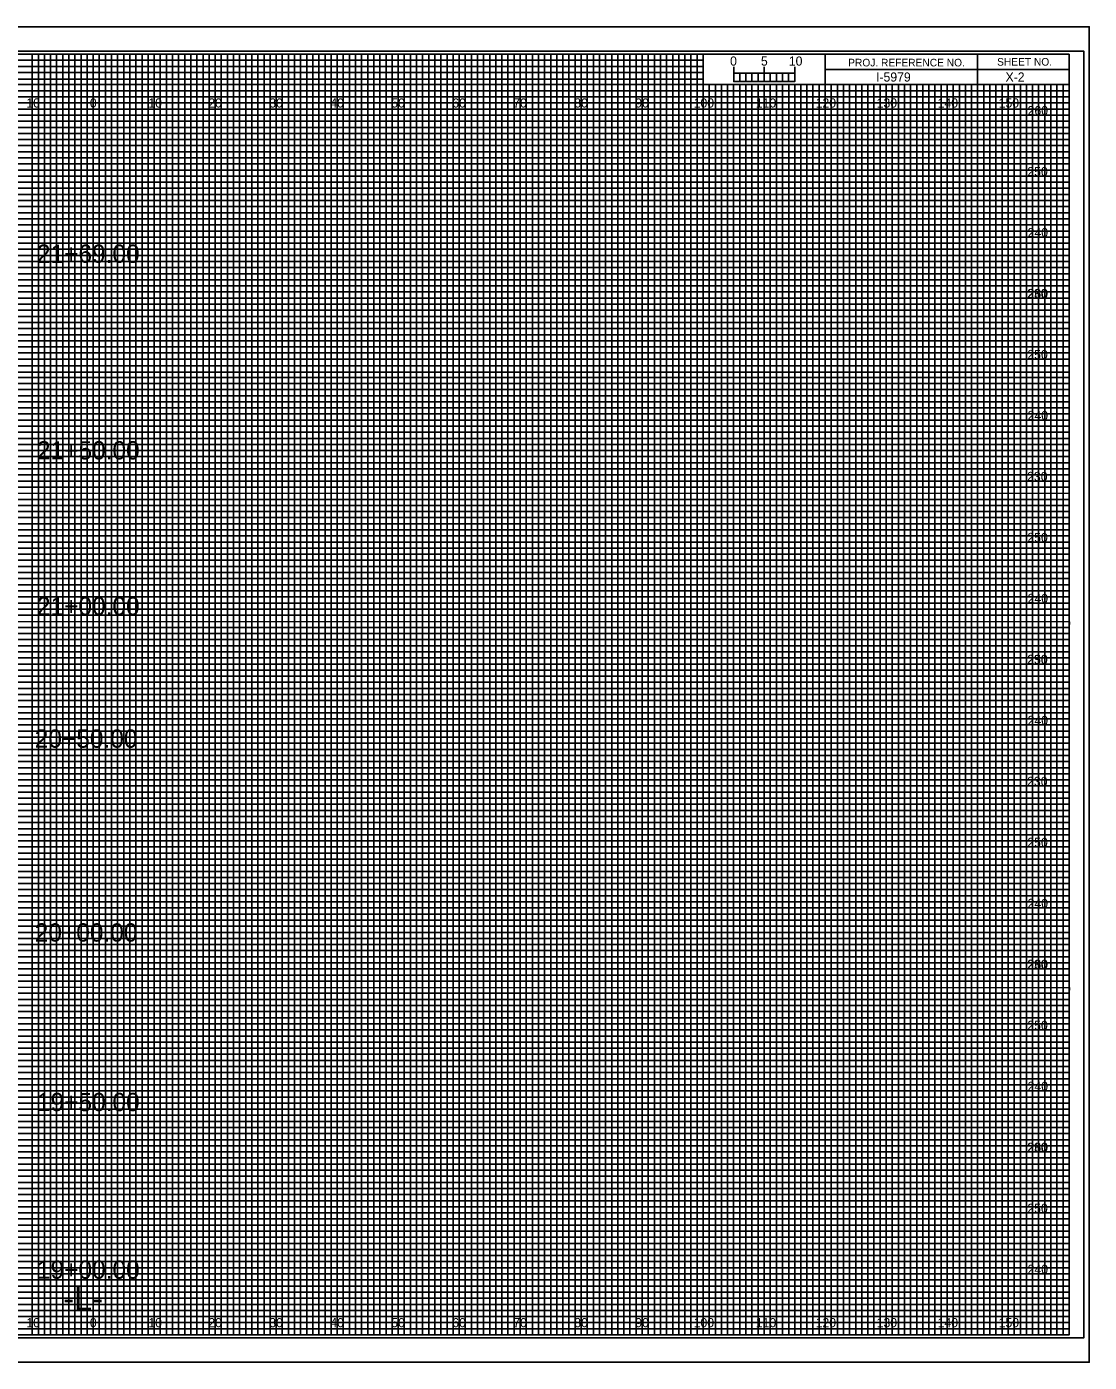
# Model space of a CAD drawing. Extents: x -13 to 359, y -5 to 2854.
# Drawn here: x 149.1 to 323.3, y 215.5 to 434.5 of the extents above; entities that cross this region are included whole.
import ezdxf

# ---------------------------------------------------------------- set-up
doc = ezdxf.new("R2010")
doc.units = 0
for name, color, linetype in [('Exist CMT Pavement', 7, 'Continuous'), ('Exist Cross Section Cell', 7, 'Continuous'), ('Exist XS Ground Line', 7, 'Continuous'), ('Prop CMT Conc Surface', 7, 'Continuous'), ('Prop CMT Concrete Structures', 7, 'Continuous'), ('Prop CMT DNC', 7, 'Continuous'), ('Prop CMT Pvmt Course 1', 7, 'Continuous'), ('Prop CMT Pvmt Course 1 CG', 7, 'Continuous'), ('Prop CMT Pvmt Course 1 Wedge', 7, 'Continuous'), ('Prop CMT Pvmt Course 2', 7, 'Continuous'), ('Prop CMT Pvmt Course 2 Wedge', 7, 'Continuous'), ('Prop CMT Pvmt Course 3', 7, 'Continuous'), ('Prop CMT Pvmt Course 3 Wedge', 7, 'Continuous'), ('Prop CMT Shear Line', 7, 'Continuous'), ('Prop CMT Slope Grass', 7, 'Continuous'), ('Prop CMT Subgrade Earthwork', 7, 'Continuous'), ('Scratch_Level_0', 7, 'Continuous')]:
    doc.layers.add(name, color=color, linetype=linetype)

msp = doc.modelspace()

# ---------------------------------------------------------------- linework, layer by layer
at = {"layer": 'Exist XS Ground Line'}
for p, q in [((150, 430), (140, 430)), ((150, 220), (150, 430)), ((170, 430), (160, 430)), ((160, 430), (160, 220)), ((170, 220), (170, 430)), ((190, 430), (180, 430)), ((180, 430), (180, 220)), ((190, 220), (190, 430)), ((210, 430), (200, 430)), ((200, 430), (200, 220)), ((210, 220), (210, 430)), ((230, 430), (220, 430)), ((220, 430), (220, 220)), ((230, 220), (230, 430)), ((250, 430), (240, 430)), ((240, 430), (240, 220)), ((250, 220), (250, 430)), ((260, 430), (260, 220)), ((270, 220), (270, 425)), ((290, 425), (280, 425)), ((280, 425), (280, 220)), ((290, 220), (290, 425)), ((310, 425), (300, 425)), ((300, 425), (300, 220)), ((310, 220), (310, 425)), ((160, 220), (150, 220)), ((180, 220), (170, 220)), ((200, 220), (190, 220)), ((220, 220), (210, 220)), ((240, 220), (230, 220)), ((260, 220), (250, 220)), ((280, 220), (270, 220)), ((300, 220), (290, 220)), ((320, 220), (310, 220)), ((320, 220), (320, 220))]:
    msp.add_line(p, q, dxfattribs=at)
for points in [[(0, 420), (320, 420), (320, 410), (0, 410)], [(0, 400), (320, 400), (320, 390), (0, 390)], [(0, 380), (320, 380), (320, 370), (0, 370)], [(0, 360), (320, 360), (320, 350), (0, 350)], [(0, 340), (320, 340), (320, 330), (0, 330)], [(0, 320), (320, 320), (320, 310), (0, 310)], [(0, 300), (320, 300), (320, 290), (0, 290)], [(0, 280), (320, 280), (320, 270), (0, 270)], [(0, 260), (320, 260), (320, 250), (0, 250)], [(0, 240), (320, 240), (320, 230), (0, 230)]]:
    msp.add_lwpolyline(points, dxfattribs=at)
at = {"layer": 'Prop CMT Conc Surface'}
for p, q in [((265, 425.49), (265, 427.9)), ((265, 426.9), (265, 427.9)), ((270, 425.49), (270, 427.9)), ((275, 425.49), (275, 427.9)), ((275, 426.9), (275, 427.9))]:
    msp.add_line(p, q, dxfattribs=at)
for points in [[(275, 426.9), (265, 426.9), (265, 425.49), (275, 425.49)], [(265, 426.9), (266, 426.9), (266, 425.49), (265, 425.49)], [(267, 426.9), (268, 426.9), (268, 425.49), (267, 425.49)], [(269, 426.9), (270, 426.9), (270, 425.49), (269, 425.49)], [(271, 426.9), (272, 426.9), (272, 425.49), (271, 425.49)], [(273, 426.9), (274, 426.9), (274, 425.49), (273, 425.49)]]:
    msp.add_lwpolyline(points, close=True, dxfattribs=at)
at = {"layer": 'Prop CMT Concrete Structures'}
for p, q in [((305, 430), (305, 425)), ((305, 425), (305, 430)), ((280, 427.5), (280, 425)), ((320, 427.49), (280, 427.49)), ((280, 425), (320, 425))]:
    msp.add_line(p, q, dxfattribs=at)
for points in [[(320, 430), (0, 430), (0, 220), (320, 220)], [(280, 430), (260, 430), (260, 425.03), (280, 425.03)], [(320, 430), (280, 430), (280, 425), (320, 425)]]:
    msp.add_lwpolyline(points, close=True, dxfattribs=at)
at = {"layer": 'Prop CMT DNC'}
for p, q in [((323.3, 434.5), (-13.4, 434.5)), ((-13.4, 215.5), (323.3, 215.5))]:
    msp.add_line(p, q, dxfattribs=at)
at = {"layer": 'Prop CMT Pvmt Course 1'}
for p, q in [((0, 429), (260, 429)), ((260, 427.98), (0, 427.98)), ((260, 429), (260, 427.98)), ((0, 427), (260, 427)), ((260, 425.89), (0, 425.89)), ((260, 427), (260, 425.89)), ((0, 424), (320, 424))]:
    msp.add_line(p, q, dxfattribs=at)
for points in [[(0, 423), (270, 423), (320, 423), (320, 422), (0, 422)], [(0, 421), (320, 421), (320, 419), (0, 419)], [(0, 418), (320, 418), (320, 417), (0, 416.98)], [(0, 416), (320, 416), (320, 414), (0, 414)], [(0, 413), (320, 413), (320, 412), (0, 412)], [(0, 411), (320, 411), (320, 409), (0, 409)], [(0, 408), (320, 408), (320, 407), (0, 407)], [(0, 406), (320, 406), (320, 404), (0, 404)], [(0, 403), (320, 403), (320, 402), (0, 402)], [(0, 401), (320, 401), (320, 399), (0, 399)], [(0, 398), (320, 398), (320, 397), (0, 397)], [(0, 396), (320, 396), (320, 393.95), (320, 393), (320, 392), (0, 392)], [(0, 394), (320, 394), (320, 393), (0, 393)], [(0, 391), (320, 391), (320, 389), (0, 389.03)], [(0, 389.03), (320, 389), (320, 388), (0, 388)], [(0, 387), (320, 387), (320, 386), (0, 386)], [(0, 384), (320, 384), (320, 383), (0, 383)], [(0, 382), (320, 382), (320, 381), (0, 381)], [(-0.07, 378.89), (320, 378.89), (320, 377.88), (-0.07, 377.88)], [(0, 377), (320, 377), (320, 376), (0, 376)], [(0, 374), (320, 374), (320, 373), (0, 373)], [(0, 372), (320, 372), (320, 371), (0, 371)], [(0, 369), (320, 369), (320, 368), (0, 368)], [(0, 367), (320, 367), (320, 366), (0, 366)], [(0, 364), (320, 364), (320, 363), (0, 363)], [(0, 362), (320, 362), (320, 361), (0, 361)], [(0, 359), (320, 359), (319.99, 357.98), (0, 358)], [(0, 357), (320, 357), (320, 356), (0, 356)], [(0, 354), (320, 354), (320, 353), (0, 353)], [(0, 352), (320, 352), (320, 351), (0, 351)], [(0, 349), (320, 349), (320, 348), (0, 348)], [(0, 347), (320, 347), (320, 346), (0, 346)], [(0, 344), (320, 344), (320, 343), (0, 343)], [(0, 342), (320, 342), (320, 341), (0, 341)], [(0, 339), (320, 339), (320, 338), (0, 338)], [(0, 336.99), (320.07, 336.91), (320, 336), (0, 336)], [(0, 334), (320, 334), (320, 333), (0, 333)], [(0, 332), (320, 332), (320, 331), (0, 331)], [(0, 329), (320, 329), (320, 328), (0, 328)], [(0, 327), (320, 327), (320, 326), (0, 326)], [(0, 324), (320, 324), (320, 323), (0, 323)], [(0, 322), (320, 322), (320, 321), (0, 321)], [(0, 319), (320, 319), (320, 318), (0, 318)], [(0, 317), (320, 317), (320, 316), (0, 316)], [(0, 314), (320, 314), (320, 313), (0, 313)], [(0, 312), (320, 312), (320, 311), (0, 311)], [(0, 309), (320, 309), (320, 308), (0, 308)], [(0, 307), (320, 307), (320, 306), (0, 306)], [(0, 304), (320, 304), (320, 303), (0, 303)], [(0, 302), (320, 302), (320, 301), (0, 301)], [(0, 299), (320, 299), (319.99, 297.98), (0, 298)], [(0, 297), (320, 297), (320, 296), (0, 296)], [(0, 294), (320, 294), (320, 293), (0, 293)], [(0, 292), (320, 292), (320, 291), (0, 291)], [(0, 289), (320, 289), (320, 288), (0, 288)], [(0, 287), (320, 287), (320, 286), (0, 286)], [(0, 284), (320, 284), (320, 283), (0, 283)], [(0, 282), (320, 282), (320, 281), (0, 281)], [(0, 279), (320, 279), (320, 278), (0, 278)], [(0, 276.99), (320.07, 276.91), (320, 276), (0, 276)], [(0, 274), (320, 274), (320, 273), (0, 273)], [(0, 272), (320, 272), (320, 271), (0, 271)], [(0, 269), (320, 269), (320, 268), (0, 268)], [(0, 267), (320, 267), (320, 266), (0, 266)], [(0, 264), (320, 264), (320, 263), (0, 263)], [(0, 262), (320, 262), (320, 261), (0, 261)], [(0, 259), (320, 259), (320, 258), (0, 258)], [(0, 257), (320, 257), (320, 256), (0, 256)], [(0, 254), (320, 254), (320, 253), (0, 253)], [(0, 252), (320, 252), (320, 251), (0, 251)], [(0, 249), (320, 249), (320, 248), (0, 248)], [(0, 247), (320, 247), (320, 246), (0, 246)], [(0, 244), (320, 244), (320, 243), (0, 243)], [(0, 242), (320, 242), (320, 241), (0, 241)], [(0, 239), (320, 239), (320, 238), (0, 238)], [(0, 237), (320, 237), (320, 236), (0, 236)], [(0, 234), (320, 234), (320, 233), (0, 233)], [(0, 232), (320, 232), (320, 231), (0, 231)], [(0, 229), (320, 229), (320, 228), (0, 228)], [(0, 227), (320, 227), (320, 226), (0, 226)], [(0, 224), (320, 224), (320, 223), (0, 223)], [(0, 222), (320, 222), (320, 221), (0, 221)]]:
    msp.add_lwpolyline(points, dxfattribs=at)
at = {"layer": 'Prop CMT Pvmt Course 1 CG'}
for p, q in [((267, 425), (266.01, 425)), ((266.01, 425), (266.01, 220)), ((267, 220), (267, 425)), ((269, 425), (268, 425)), ((268, 425), (268, 220)), ((269, 220), (269, 425)), ((266.01, 220), (265, 220)), ((268, 220), (267, 220))]:
    msp.add_line(p, q, dxfattribs=at)
for points in [[(150, 220), (151, 220), (151, 430), (152, 430), (152, 220)], [(152, 220), (153, 220), (153, 430), (154, 430), (154, 220)], [(155, 220), (156, 220), (156, 430), (157, 430), (157, 220)], [(157, 220), (158, 220), (158, 430), (159, 430), (159, 220)], [(160, 220), (161, 220), (161, 430), (162, 430), (162, 220)], [(162, 220), (163, 220), (163, 430), (164, 430), (164, 220)], [(165, 220), (166, 220), (166, 430), (167, 430), (167, 220)], [(167, 220), (168, 220), (168, 430), (169, 430), (169, 220)], [(170, 220), (171, 220), (171, 430), (172, 430), (172, 220)], [(172, 220), (173, 220), (173, 430), (174, 430), (174, 220)], [(175, 220), (176, 220), (176, 430), (177, 430), (177, 220)], [(177, 220), (178, 220), (178, 430), (179, 430), (179, 220)], [(180, 220), (181, 220), (181, 430), (182, 430), (182, 220)], [(182, 220), (183, 220), (183, 430), (184, 430), (184, 220)], [(185, 220), (186, 220), (186, 430), (187, 430), (187, 220)], [(187, 220), (188, 220), (188, 430), (189, 430), (189, 220)], [(190, 220), (191, 220), (191, 430), (192, 430), (192, 220)], [(192, 220), (193, 220), (193, 430), (194, 430), (194, 220)], [(195, 220), (196, 220), (196, 430), (197, 430), (197, 220)], [(197, 220), (198, 220), (198, 430), (199, 430), (199, 220)], [(200, 220), (201, 220), (201, 430), (202, 430), (202, 220)], [(202, 220), (203, 220), (203, 430), (204, 430), (204, 220)], [(205, 220), (206, 220), (206, 430), (207, 430), (207, 220)], [(207, 220), (208, 220), (208, 430), (209, 430), (209, 220)], [(210, 220), (211, 220), (211, 430), (212, 430), (212, 220)], [(212, 220), (213, 220), (213, 430), (214, 430), (214, 220)], [(215, 220), (216, 220), (216, 430), (217, 430), (217, 220)], [(217, 220), (218, 220), (218, 430), (219, 430), (219, 220)], [(220, 220), (221, 220), (221, 430), (222, 430), (222, 220)], [(222, 220), (223, 220), (223, 430), (224, 430), (224, 220)], [(225, 220), (226, 220), (226, 430), (227, 430), (227, 220)], [(227, 220), (228, 220), (228, 430), (229, 430), (229, 220)], [(230, 220), (231, 220), (231, 430), (232, 430), (232, 220)], [(232, 220), (233, 220), (233, 430), (234, 430), (234, 220)], [(235, 220), (236, 220), (236, 430), (237, 430), (237, 220)], [(237, 220), (238, 220), (238, 430), (239, 430), (239, 220)], [(240, 220), (241, 220), (241, 430), (242, 430), (242, 220)], [(242, 220), (243, 220), (243, 430), (244, 430), (244, 220)], [(245, 220), (246, 220), (246, 430), (247, 430), (247, 220)], [(247, 220), (248, 220), (248, 430), (249, 430), (249, 220)], [(250, 220), (251, 220), (251, 430), (252, 430), (252, 220)], [(252, 220), (253, 220), (253, 430), (254, 430), (254, 220)], [(255, 220), (256, 220), (256, 430), (257, 430), (257, 220)], [(257, 220), (258, 220), (258, 430), (259, 430), (259, 220)], [(260, 220), (261, 220), (261, 425), (262.02, 425), (262.02, 220)], [(262, 220), (263, 220), (263, 425), (263.99, 425), (263.99, 220)], [(270, 220), (270.98, 220), (270.98, 425), (272, 425), (272, 220)], [(272, 220), (273, 220), (273, 425), (274.05, 425), (274.05, 220)], [(275, 220), (276, 220), (276, 425), (277, 425), (277, 220)], [(277, 220), (278, 220), (278, 425), (279, 425), (279, 220)], [(280, 220), (281, 220), (281, 425), (282, 425), (282, 220)], [(282, 220), (283, 220), (283, 425), (284, 425), (284, 220)], [(285, 220), (286, 220), (286, 425), (287, 425), (287, 220)], [(287, 220), (288, 220), (288, 425), (289, 425), (289, 220)], [(290, 220), (291, 220), (291, 425), (292, 425), (292, 220)], [(292, 220), (293, 220), (293, 425), (294, 425), (294, 220)], [(295, 220), (296, 220), (296, 425), (297, 425), (297, 220)], [(297, 220), (298, 220), (298, 425), (299, 425), (299, 220)], [(300, 220), (301, 220), (301, 425), (302, 425), (302, 220)], [(302, 220), (303, 220), (303, 425), (304, 425), (304, 220)], [(305, 220), (306, 220), (306, 425), (307, 425), (307, 220)], [(307, 220), (308, 220), (308, 425), (309, 425), (309, 220)], [(310, 220), (311, 220), (311, 425), (312, 425), (312, 220)], [(312, 220), (313, 220), (313, 425), (314, 425), (314, 220)], [(315, 220), (316, 220), (316, 425), (317, 425), (317, 220)], [(317, 220), (318, 220), (318, 425), (319, 425), (319, 220)]]:
    msp.add_lwpolyline(points, dxfattribs=at)
at = {"layer": 'Prop CMT Shear Line'}
for p, q in [((150, 220), (150, 430)), ((160, 220), (160, 430)), ((170, 220), (170, 430)), ((180, 220), (180, 430)), ((190, 220), (190, 430)), ((200, 220), (200, 430)), ((210, 220), (210, 430)), ((220, 220), (220, 430)), ((230, 220), (230, 430)), ((240, 220), (240, 430)), ((250, 220), (250, 430)), ((260, 220), (260, 424.69)), ((270, 220), (270, 424.69)), ((280, 220), (280, 424.69)), ((290, 220), (290, 424.69)), ((300, 220), (300, 424.69)), ((310, 220), (310, 424.69)), ((0, 420), (320, 420)), ((0, 410), (320, 410)), ((0, 400), (320, 400)), ((0, 390), (320, 390)), ((0, 380), (320, 380)), ((0, 370), (320, 370)), ((0, 360), (320, 360)), ((0, 350), (320, 350)), ((0, 340), (320, 340)), ((0, 330), (320, 330)), ((0, 320), (320, 320)), ((0, 310), (320, 310)), ((0, 300), (320, 300)), ((0, 290), (320, 290)), ((0, 280), (320, 280)), ((0, 270), (320, 270)), ((0, 260), (320, 260)), ((0, 250), (320, 250)), ((0, 240), (320, 240)), ((0, 230), (320, 230))]:
    msp.add_line(p, q, dxfattribs=at)
at = {"layer": 'Prop CMT Slope Grass'}
msp.add_lwpolyline([(-10.8, 219.5), (322.4, 219.5), (322.4, 430.5), (-10.8, 430.5)], close=True, dxfattribs=at)
at = {"layer": 'Prop CMT Subgrade Earthwork'}
msp.add_lwpolyline([(-13.4, 215.5), (323.3, 215.5), (323.3, 434.5), (-13.4, 434.5)], close=True, dxfattribs=at)
at = {"layer": 'Scratch_Level_0'}
for points in [[(145, 220), (155, 220), (155, 430), (165, 430), (165, 220), (175, 220), (175, 430), (185, 430), (185, 220), (195, 220), (195, 430), (205, 430), (205, 220), (215, 220), (215, 430), (225, 430), (225, 220), (235, 220), (235, 430), (245, 430), (245, 220), (255, 220), (255, 430), (259.93, 430), (260, 430), (260, 425), (264.99, 425), (264.99, 220), (275, 220), (275, 425), (285, 425), (285, 220), (295, 220), (295, 425), (305, 425), (305, 220), (315, 220), (315, 425)], [(0, 425), (275, 425)], [(0, 405), (320, 405), (320, 415), (0, 415)], [(0, 385), (320, 385), (320, 395), (0, 395)], [(0, 365), (320, 365), (320, 375), (0, 375)], [(0, 345), (320, 345), (320, 355), (0, 355)], [(0, 325), (320, 325), (320, 335), (0, 335)], [(0, 305), (320, 305), (320, 315), (0, 315)], [(0, 285), (320, 285), (320, 295), (0, 295)], [(0, 265), (320, 265), (320, 275), (0, 275)], [(0, 245), (320, 245), (320, 255), (0, 255)], [(0, 225), (320, 225), (320, 235), (0, 235)]]:
    msp.add_lwpolyline(points, dxfattribs=at)

# ---------------------------------------------------------------- texts
at = {"layer": 'Exist CMT Pavement'}
for s, p in [('5', (269.47, 428.12)), ('10', (274.04, 428.12))]:
    msp.add_text(s, height=1.5, dxfattribs=at).set_placement(p)
at = {"layer": 'Exist Cross Section Cell'}
for s, p in [('10', (149.04, 421.25)), ('0', (159.45, 421.25)), ('0', (159.45, 421.25)), ('10', (169.04, 421.25)), ('20', (178.86, 421.25)), ('30', (188.86, 421.25)), ('40', (198.86, 421.25)), ('50', (208.86, 421.25)), ('60', (218.86, 421.25)), ('70', (228.86, 421.25)), ('80', (238.86, 421.25)), ('90', (248.86, 421.25)), ('100', (258.44, 421.25)), ('110', (268.62, 421.25)), ('120', (278.44, 421.25)), ('130', (288.44, 421.25)), ('140', (298.44, 421.25)), ('150', (308.44, 421.25)), ('10', (149.04, 221.25)), ('0', (159.45, 221.25)), ('0', (159.45, 221.25)), ('10', (169.04, 221.25)), ('20', (178.86, 221.25)), ('30', (188.86, 221.25)), ('40', (198.86, 221.25)), ('50', (208.86, 221.25)), ('60', (218.86, 221.25)), ('70', (228.86, 221.25)), ('80', (238.86, 221.25)), ('90', (248.86, 221.25)), ('100', (258.44, 221.25)), ('110', (268.62, 221.25)), ('120', (278.44, 221.25)), ('130', (288.44, 221.25)), ('140', (298.44, 221.25)), ('150', (308.44, 221.25))]:
    msp.add_text(s, height=1.5, dxfattribs=at).set_placement(p)
at = {"layer": 'Prop CMT Conc Surface'}
msp.add_text('0', height=1.5, dxfattribs=at).set_placement((264.41, 428.12))
at = {"layer": 'Prop CMT Concrete Structures'}
for s, p in [('PROJ. REFERENCE NO.', (283.77, 427.99)), ('SHEET NO.', (308.19, 428.12))]:
    msp.add_text(s, height=1.25, dxfattribs=at).set_placement(p)
at = {"layer": 'Prop CMT Pvmt Course 1 Wedge'}
msp.add_text('X-2', height=1.5, dxfattribs=at).set_placement((309.57, 425.5))
at = {"layer": 'Prop CMT Pvmt Course 2'}
for s, p in [('260', (313.19, 420)), ('250', (313.15, 410)), ('240', (313.19, 400)), ('230', (313.11, 390)), ('260', (313.19, 390)), ('250', (313.15, 380)), ('240', (313.19, 370)), ('230', (313.11, 360)), ('250', (313.15, 350)), ('240', (313.19, 340)), ('230', (313.11, 330)), ('250', (313.15, 330)), ('240', (313.19, 320)), ('230', (313.11, 310)), ('250', (313.15, 300)), ('240', (313.19, 290)), ('230', (313.11, 280)), ('260', (313.19, 280)), ('250', (313.15, 270)), ('240', (313.19, 260)), ('230', (313.11, 250)), ('260', (313.19, 250)), ('250', (313.15, 240)), ('240', (313.19, 230))]:
    msp.add_text(s, height=1.5, dxfattribs=at).set_placement(p)
at = {"layer": 'Prop CMT Pvmt Course 2 Wedge'}
msp.add_text('I-5979', height=1.5, dxfattribs=at).set_placement((288.34, 425.5))
at = {"layer": 'Prop CMT Pvmt Course 3'}
for s, p in [('21+69.00', (150.77, 395.78)), ('21+50.00', (150.77, 363.54)), ('21+00.00', (150.77, 338)), ('20+50.00', (150.41, 316.27)), ('20+00.00', (150.41, 284.48)), ('19+50.00', (150.77, 256.68)), ('19+00.00', (150.77, 229.2))]:
    msp.add_text(s, height=3, dxfattribs=at).set_placement(p)
at = {"layer": 'Prop CMT Pvmt Course 3 Wedge'}
msp.add_text('-L-', height=4, dxfattribs=at).set_placement((155.06, 224))

doc.saveas('drawing.dxf')
